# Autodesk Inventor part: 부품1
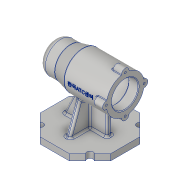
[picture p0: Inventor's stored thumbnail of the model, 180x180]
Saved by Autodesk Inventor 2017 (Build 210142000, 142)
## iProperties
Created: 2019-12
Part Number: 부품1
Material: 알루미늄 6061
Document SubType Name: Modeling
Designer: 5-07-le-1
Density: 2.7 g/cm^3
Appearance: 알루미늄 - 평지
Mass: 725.811 g
Surface Area: 714.792 cm^2
Volume: 268.819 cm^3
Author: 5-07-le-1
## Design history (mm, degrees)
sketch "스케치1" dims "d0" = 112
  geometry: L1 (23.196, 56)-(56, 23.196); L2 (56, 23.196)-(56, -23.196); L3 (56, -23.196)-(23.196, -56); L4 (23.196, -56)-(-23.196, -56); L5 (-23.196, -56)-(-56, -23.196); L6 (-56, -23.196)-(-56, 23.196); L7 (-56, 23.196)-(-23.196, 56); L8 (-23.196, 56)-(23.196, 56); 4 further points
  constraints: 16 end point, 2 coincident, 1 midpoint, 1 vertical alignment, 19 other
extrude "돌출1" new body sketch "스케치1" distance "d1" = 10; taper "d2" = 0 deg
sketch "스케치2"
  geometry: L1 (0, 0)-(-56, 0); L2 (0, 0)-(-39.598, 39.598); L3 (-56, 23.196)-(-23.196, 56) reference; L4 (0, 0)-(39.598, 39.598); L5 (0, 0)-(39.598, -39.598); L6 (0, 0)-(-39.598, -39.598); C1 r 5 at (-39.598, 39.598); C2 r 5 at (39.598, 39.598); C3 r 5 at (39.598, -39.598); C4 r 5 at (-39.598, -39.598)
  constraints: 10 end point, 4 centre point, 4 coincident, 3 equal radius, 1 horizontal, 1 midpoint, 1 perpendicular
  dimensions: "d4" = 45 deg angle of L1 L2; "d5" = 10 diameter of C1; "d6" = 90 deg angle of L5 L4
extrude "돌출2" cut sketch "스케치2" stored distance "d7" = 10; taper "d8" = 0 deg
sketch "스케치3"
  geometry: L1 (-56, 80)-(56, 80); L2 (0, 0)-(0, 80); L3 (-56, 80)-(-56, 105); L4 (-56, 105)-(-31, 105); L5 (-31, 105)-(-11, 110); L6 (-11, 110)-(56, 110); L7 (56, 110)-(56, 80); L8 (56, 101)-(41, 101); L9 (41, 101)-(41, 104); L10 (41, 104)-(-13, 104); L11 (-13, 104)-(-13, 101); L12 (-13, 101)-(-25, 101); L13 (-25, 101)-(-25, 97.5); L14 (-25, 97.5)-(-43, 97.5); L15 (-43, 97.5)-(-43, 96); L16 (-43, 96)-(-47, 96); L17 (-47, 96)-(-47, 90.5); L18 (-47, 90.5)-(-50, 90.5); L19 (-50, 90.5)-(-50, 80)
  constraints: 38 end point, 12 perpendicular, 4 horizontal, 4 point on line, 2 midpoint, 1 vertical
  dimensions: "d9" = 112 distance of L1.start L1.end; "d10" = 80 distance of L2.start L2.end; "d11" = 50 diameter of L4 L1; "d12" = 60 diameter of L6 L1; "d13" = 25 distance of L3.end L4.end; "d14" = 45 distance from line of L3 L5.end; "d15" = 21 diameter of L18 L1; "d16" = 32 diameter of L16 L1; "d17" = 35 diameter of L14 L1; "d18" = 42 diameter of L12 L1; "d19" = 48 diameter of L10 L1; "d20" = 3 distance of L17.end L18.end; "d21" = 4 distance of L15.end L16.end; "d22" = 18 distance of L13.end L14.end; "d23" = 12 distance of L11.end L12.end; "d24" = 54 distance of L9.end L10.end; "d26" = 15 distance of L8.start L8.end
revolve "회전1" sketch "스케치3" stored, may be unused: angle "d27" = 90 deg
fillet "모깎기1" dims "d36" = 3
fillet "모깎기2" dims "d37" = 0.3
fillet "모깎기3" dims "d38" = 3
chamfer "모따기1" distance "d39" = 1; stored, may be unused: second distance "d40" = 2, angle "d41" = 45 deg
fillet "모깎기4" dims "d42" = 3
fillet "모깎기5" dims "d43" = 10
sketch "스케치8"
  geometry: L1 (-10.631, 110)-(56, 110) reference; L2 (56, 50)-(56, 110) reference; L3 (56, 110)-(40, 110); L4 (56, 110)-(56, 116); L5 (56, 116)-(40, 116); L6 (40, 116)-(40, 110); 1 further point
  constraints: 8 end point, 2 perpendicular, 1 point on line, 1 vertical
  dimensions: "d47" = 16 distance of L1.end L3.end; "d48" = 6 distance of L1.end L4.end
revolve "회전2" sketch "스케치8" stored, may be unused: angle "d49" = 90 deg
sketch "스케치9"
  geometry: A1 r 30 centre (0, 0) between (0, 30) and (0, 30) reference; 2 further points
  constraints: 1 point on circle
hole "구멍1" sketch "스케치9" at (0, 30) diameter "d51" = 3.242; stored, may be unused: countersink angle "d55" = 90 deg, drill point angle "d57" = 118 deg; dims "d52" = 8, "d53" = 4, "d54" = 2, "d56" = 11
fillet "모깎기6" dims "d58" = 3
fillet "모깎기7" dims "d59" = 1
sketch "스케치11"
  geometry: L1 (10, -56)-(10, -43.134) reference; L2 (10, -34.598)-(10, -43.134) reference; L3 (10, -36.062)-(10, -23.196) reference; L4 (10, -23.196)-(10, 23.196) reference; L5 (10, 23.196)-(10, 36.062) reference; L6 (10, 43.134)-(10, 34.598) reference; L7 (10, 43.134)-(10, 56) reference; L8 (56.766, -18.979)-(10, -36); L9 (0, -56)-(10, -56) reference; L10 (50, 0)-(10, 0); C1 r 25 at (80, 0) reference; C2 r 29.91 at (80, 0) reference; A1 r 30 centre (80, 0) between (50.774, -6.771) and (73.229, -29.226) reference; A2 r 30 centre (80, 0) between (50.129, 2.779) and (50.129, -2.779) reference; A3 r 30 centre (80, 0) between (73.229, 29.226) and (50.774, 6.771) reference; A4 r 30 centre (80, 0) between (82.779, 29.871) and (77.221, 29.871) reference; A5 r 30 centre (80, 0) between (109.226, 6.771) and (86.771, 29.226) reference; A6 r 30 centre (80, 0) between (109.871, -2.779) and (109.871, 2.779) reference; A7 r 30 centre (80, 0) between (86.771, -29.226) and (109.226, -6.771) reference; A8 r 30 centre (80, 0) between (77.221, -29.871) and (82.779, -29.871) reference; A9 r 30 centre (80, 0) between (56.766, -18.979) and (50, 0) reference; 9 further points
  constraints: 4 end point, 4 point on circle, 2 midpoint, 1 point on line, 8 other
  dimensions: "d67" = 20 distance from line of L9 L8.end; "d68" = 110 deg angle of L2 L8
extrude "돌출4" join sketch "스케치11" stored distance "d69" = 8; taper "d70" = 0 deg
sketch "스케치12"
  geometry: 1 further point
sketch "스케치13"
  geometry: L1 (-30.642, 54.91)-(-11.358, 50.09) reference; L2 (-10.631, 50)-(39, 50) reference; L3 (-56, 10)-(-43.134, 10) reference; L4 (-43.134, 10)-(-34.598, 10) reference; L5 (-36.062, 10)-(-23.196, 10) reference; L6 (-23.196, 10)-(23.196, 10) reference; L7 (23.196, 10)-(36.062, 10) reference; L8 (34.598, 10)-(43.134, 10) reference; L9 (43.134, 10)-(56, 10) reference; L10 (-18.476, 51.869)-(-38, 10); L11 (-23.196, 10)-(-36.062, 10) reference; L12 (-56, 0)-(-56, 10) reference; L13 (31, 50)-(31, 10); L14 (36.062, 10)-(23.196, 10) reference; L15 (56, 0)-(56, 10) reference; L16 (-18.476, 51.869)-(-17.327, 54.334); L17 (-17.327, 54.334)-(31, 54.334); L18 (31, 54.334)-(31, 50); L19 (-38, 10)-(31, 10); L20 (-34.598, 10)-(-34.598, 0) reference; 1 further point
  constraints: 12 end point, 4 point on line, 3 perpendicular, 1 horizontal
  dimensions: "d71" = 18 distance from line of L12 L10.end; "d72" = 115 deg angle of L4 L10; "d73" = 25 distance from line of L15 L13.end
extrude "돌출5" join sketch "스케치13" stored distance "d74" = 8; taper "d75" = 0 deg
fillet "모깎기8" dims "d76" = 3
fillet "모깎기9" dims "d77" = 3
sketch "스케치14"
  geometry: L1 (80, 0)-(80, 30); A1 r 30 centre (80, 0) between (50.683, -6.364) and (50.683, 6.364) reference; A2 r 30 centre (80, 0) between (54.572, 15.918) and (50.683, 6.364) reference; A3 r 30 centre (80, 0) between (54.572, 15.918) and (50.683, 6.364) reference; A4 r 30 centre (80, 0) between (50.014, 0.909) and (50.014, -0.909) reference; A5 r 30 centre (80, 0) between (50.683, -6.364) and (54.572, -15.918) reference; A6 r 30 centre (80, 0) between (50.683, -6.364) and (54.572, -15.918) reference; A7 r 30 centre (80, 0) between (50.774, -6.771) and (73.229, -29.226) reference; A8 r 30 centre (80, 0) between (50.129, 2.779) and (50.129, -2.779) reference; A9 r 30 centre (80, 0) between (73.229, 29.226) and (50.774, 6.771) reference; A10 r 30 centre (80, 0) between (82.779, 29.871) and (77.221, 29.871) reference; A11 r 30 centre (80, 0) between (109.226, 6.771) and (86.771, 29.226) reference; A12 r 30 centre (80, 0) between (109.871, -2.779) and (109.871, 2.779) reference; A13 r 30 centre (80, 0) between (86.771, -29.226) and (109.226, -6.771) reference; A14 r 30 centre (80, 0) between (77.221, -29.871) and (82.779, -29.871) reference; 15 further points
  constraints: 2 end point, 1 point on circle, 14 other
  node "투영된 루프3"
node "작업 평면2"
  node "작업 평면1"
sketch "스케치15"
  geometry: L1 (-5.739, 3.002)-(35.739, 3.002); L2 (35.739, 3.002)-(35.739, -3.002); L3 (35.739, -3.002)-(-5.739, -3.002); L4 (-5.739, -3.002)-(-5.739, 3.002); L5 (15, 3.002)-(15, -3.002); L6 (-5.739, 0)-(15, 0); L7 (56, 6.771)-(56, 29.226) reference; L8 (0, 0)-(15, 0); L9 (0, 0)-(15, 0); 2 further points
  constraints: 8 end point, 4 midpoint, 2 horizontal, 2 other
  dimensions: "d79" = 41 distance from line of L6.end L7; "d80" = 0 vertical distance of L6.end point (0, 0)
extrude "돌출6" join sketch "스케치15" stored distance "d81" = 8; taper "d82" = 0 deg
node "솔리드1"
pattern_circular "원형 패턴1" dims "d61" = 360 deg
mirror "미러1"
node "투영된 루프2"
other parameters: "d78" = 0.5
